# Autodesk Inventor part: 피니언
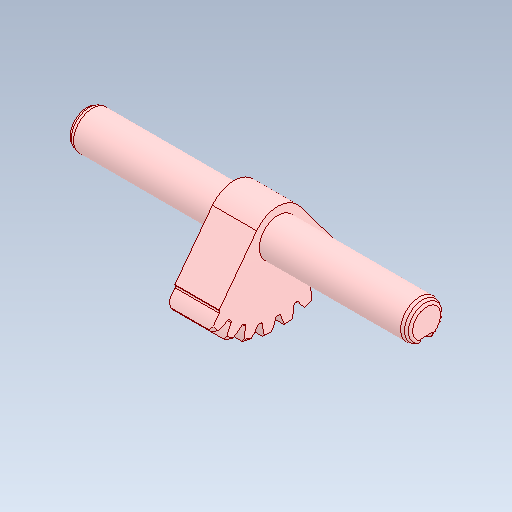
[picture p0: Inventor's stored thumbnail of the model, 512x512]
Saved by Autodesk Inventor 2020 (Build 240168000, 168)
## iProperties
Created: 2024-07
Part Number: 피니언
Material: 강철, 탄소
Document SubType Name: Modeling
Designer: oem
Density: 7.85 g/cm^3
Appearance: 기본값
Mass: 172.704 g
Surface Area: 73.4442 cm^2
Volume: 22.0005 cm^3
Sending System: Autodesk Inventor 2025
Preprocessor: ST-DEVELOPER v20
Author: jhkim
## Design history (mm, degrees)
feature "솔리드1"
node "솔리드2"
